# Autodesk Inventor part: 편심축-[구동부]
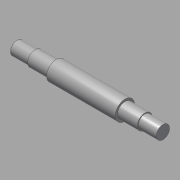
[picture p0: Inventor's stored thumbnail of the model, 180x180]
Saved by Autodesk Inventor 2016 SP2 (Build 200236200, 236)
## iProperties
Created: 2015-10
Part Number: 편심축-[구동부]
Document SubType Name: Modeling
Designer: mdu
Density: 7.86 g/cm^3
Material: 강철, 연강
Mass: 1163.82 g
Surface Area: 210.981 cm^2
Volume: 148.069 cm^3
Appearance: 강철
Author: mdu
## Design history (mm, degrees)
sketch "스케치1"
  geometry: L1 (-20.5, -41.331)-(-20.5, 32.669) reference; L2 (7.5, -30.031)-(7.5, 21.369) reference; L3 (135.5, -30.331)-(135.5, 21.669) reference; L4 (121.5, 21.369)-(121.5, -30.031) reference; L5 (184.5, -4.331)-(-7.5, -4.331); L6 (184.5, -4.331)-(184.5, 6.669); L7 (154.5, 8.169)-(121.5, 8.169); L8 (121.5, 8.169)-(121.5, 11.669); L9 (121.5, 11.669)-(7.5, 11.669); L10 (7.5, 11.669)-(7.5, 8.169); L11 (7.5, 8.169)-(-7.5, 8.169); L12 (-7.5, 8.169)-(-7.5, -4.331); L13 (154.5, 8.169)-(154.5, 6.669); L14 (154.5, 6.669)-(184.5, 6.669); C1 r 32.5 at (64.5, -4.331) reference; 1 further point
  constraints: 21 end point, 8 perpendicular, 5 point on line, 1 collinear
  dimensions: "d1" = 25 diameter of L11 L5; "d2" = 32 diameter of L9 L5; "d4" = 15 distance of L10.end L11.end; "d15" = 33 distance of L7.start L7.end; "d26" = 30 distance of L13.end L6.end; "d36" = 22 diameter of L14 L5
revolve "회전1" sketch "스케치1" stored, may be unused: angle "d6" = 90 deg
node "작업 평면1"
sketch "스케치2"
  geometry: C1 r 16 at (0, 0) reference; C2 r 20.75 at (0, 4)
  constraints: 1 centre point, 1 vertical alignment
  dimensions: "d34" = 4 distance of C2.centre C1.centre; "d35" = 41.5 diameter of C2
extrude "돌출1" join sketch "스케치2" stored distance "d9" = 40; taper "d10" = 0 deg
chamfer "모따기1" distance "d11" = 1; stored, may be unused: second distance "d12" = 2, angle "d13" = 45 deg
node "작업 평면2"
sketch "스케치3"
  geometry: L1 (-15, -10)-(-15, 10) reference; L2 (-15, 3)-(0, 3); L3 (0, -3)-(-15, -3); A1 r 3 centre (0, 0) between (0, -3) and (0, 3); 2 further points
  constraints: 4 end point, 2 perpendicular, 2 point on circle, 2 point on line, 2 tangent, 1 centre point, 1 horizontal alignment, 1 midpoint
  dimensions: "d16" = 18 dimension on A1 L1; "d17" = 6 distance between parallel lines of L3 L2
extrude "돌출2" cut sketch "스케치3" distance "d18" = 3.5; taper "d19" = 0 deg
node "솔리드1"
node "참조1"
node "참조2"
node "참조3"
node "참조4"
node "참조5"
other parameters: "d30" = 35
